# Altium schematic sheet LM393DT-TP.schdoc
size 127 x 101 mm
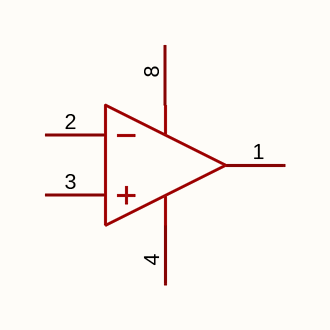
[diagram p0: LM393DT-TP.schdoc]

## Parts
U?  lm393dt-tp  [SOP-8_L4.9-W3.9-P1.27-LS6.0-BL]  (value not drawn)  (part A of 2)

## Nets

Not connected (* = marked no-connect by the designer): U? 1(OUT1) 2(IN1-) 3(IN1+) 4(VEE) 8(VCC)

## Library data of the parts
U? = lm393dt-tp: 比较器数:双路;输入失调电压(Vos):4mV;输入偏置电流(Ib):65nA;; Manufacturer: TECH PUBLIC(台舟); AddInBom: yes; ModelId: 75c24a7891ee4dd6bdac16a7163ff87e; ModelName: SOP-8_L4.9-W3.9-P1.27-LS6.0-BL-1; ModelTransform: 192.913,236.22,0,0,0,0,-0.393,2.749,0; Number of Channels: 双路; Vos - Input Offset Voltage: 4mV; Ib - Input Bias Current: 65nA; Output Type: 开集; Output Mode: MOS；CMOS；ECL；DTL；TTL; Quiescent Current: 600uA; Maximum Power Supply Range (Vdd-Vss): 30V; Single Supply: 3V~30V; Dual Supply: -15V~-1.5V；1.5V~15V; Input Offset Current(Ios): 5nA; Response Time (tr): 1.4us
